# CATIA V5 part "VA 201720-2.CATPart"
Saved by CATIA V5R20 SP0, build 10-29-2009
Part number: VA 201720-2
Revision: ANY
Definition: UNKNOWN
Nomenclature: VA 201720-2
Source: Unknown
Bounding box of the stored display mesh (mm): x -10 to 10, y 0 to 20, z -10 to 10
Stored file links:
  C:\Users\Utente\Desktop\IO LAVORO\3D X SITO CF\CUMSA\3D files VA\VA 201720\VA 201720-2.CATPart
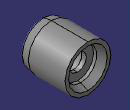
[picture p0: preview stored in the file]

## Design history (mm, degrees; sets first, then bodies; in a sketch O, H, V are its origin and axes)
Body1 "Redondeo1" (main body)
  Solid1: solid without history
